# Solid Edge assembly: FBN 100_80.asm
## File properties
Title: Zylinder
Author: bmolnar
Template: iso assembly.asm
Last saved by: bmolnar
Revision: 11
Application: Solid Edge
Username: bmolnar
Dokumentum tartalom típus: 1
Document Number: FBN 100/80
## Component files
Kolbenstange.par
Profilrohr.par
Kit.par
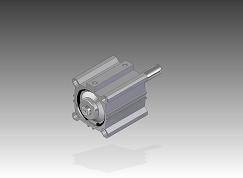
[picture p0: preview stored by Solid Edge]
